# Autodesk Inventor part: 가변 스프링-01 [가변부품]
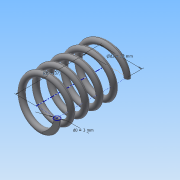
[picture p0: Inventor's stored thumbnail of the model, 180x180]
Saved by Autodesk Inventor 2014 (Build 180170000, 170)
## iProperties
Created: 2015-09
Part Number: 가변 스프링-01 [가변부품]
Material: 강철, 탄소
Document SubType Name: Modeling
Designer: study
Density: 7.87 g/cm^3
Appearance: 반연마
Mass: 18.6318 g
Surface Area: 32.4192 cm^2
Volume: 2.36745 cm^3
Author: study
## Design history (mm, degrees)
sketch "스케치1"
  geometry: L1 (0, 0)-(11, 0); L2 (11, 0)-(11, 25.358); L3 (11, 25.358)-(0, 25.358); L4 (0, 25.358)-(0, 0); C1 r 1.5 at (11, 0)
  constraints: 8 end point, 2 parallel, 1 centre point, 1 coincident, 1 horizontal, 1 perpendicular
  dimensions: "d0" = 3 diameter of C1; "d1" = 25.35829 distance of L3.end L1.start (derived); "d2" = 22 diameter of L2 L4
feature "코일1" sketch "스케치1" pitch "d3" = 10; turns "d5" = 5; dims "d4" = 25.35829 (= d1), "d6" = 0, angle "d7" = 90 deg, angle "d8" = 90 deg, "d9" = 0, "d10" = 0
sketch "스케치2"
  geometry: L1 (-12.5, 0)-(-9.5, 0) reference; 1 further point
  constraints: 1 horizontal alignment
extrude "돌출1" cut sketch "스케치2" stored distance "d11" = 10; taper "d12" = 0 deg
node "작업 평면1"
sketch "스케치3"
  geometry: L1 (-9.5, 0)-(-12.5, 0) reference; 1 further point
  constraints: 1 horizontal alignment
extrude "돌출2" cut sketch "스케치3" stored distance "d14" = 10; taper "d15" = 0 deg
node "솔리드1"
node "절단 모서리 투영1"
node "절단 모서리 투영2"
other parameters: "d13" = 25.35829 (= d1)
